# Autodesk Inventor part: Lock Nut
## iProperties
Shininess: 77.0
Length Units: 11269
Angle Units: 11279
Time Units: 11290
Mass Units: 11283
Length Display Precision: 3
Angle Display Precision: 2
Created: 2002-02
Part Number: Lock Nut
Document SubType Name: Modeling
Designer: ***
Density: 1 g/cm^3
Density: 0.0
Volumn: 0.0
Area: 0.0
PropertySet Name: Model Information
Control State: 0
Master: False
Checked Out: False
Author: ***
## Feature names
1. Extrusion1
2. Fillet1
3. Extrusion2
4. Hole1
